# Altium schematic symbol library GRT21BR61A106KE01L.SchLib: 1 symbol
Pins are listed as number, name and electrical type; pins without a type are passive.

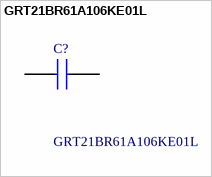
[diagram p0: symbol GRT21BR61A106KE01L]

## GRT21BR61A106KE01L
designator C?
Chip Multilayer Ceramic Capacitor Capacitance  10uF +/-10% Distance between external terminals g  0.7mm min. External terminal size e  0.2 to 0.7mm Operating Temperature Range  -55 to 85 Rated Voltage  10Vdc Size code in inch(mm)  0805 (2012M) Capacitance change rate  +/-15.0% Temperature characteristics (complied standard)  X5R(EIA) Temperature range of temperature characteristics  -55 to 85; Manufacturer_Name: Murata Electronics; Geometry.Height: 1.35mm
footprint GRT21BR61A106KE01L
pins: 1, 2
